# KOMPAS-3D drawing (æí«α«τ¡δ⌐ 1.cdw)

Referenced files in /: k6, h9, s6
Referenced files in E:\Борис\Школа\Детали машин\РГР№2\: 2.cdw
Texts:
  Трехступенчатый коническо- цилиндрический редуктор
  125 1 126 1 127 1 128 0 50 1|SPDS|125 1 126 1 127 1 128 0 50 1
  129 1 130 1 131 1 132 0 50 1|SPDS|129 1 130 1 131 1 132 0 50 1
  min
  max
  Уровень
  масла
  Технические характеристики:
  1. Частота вращения ведущего вала n   = 1455,0 об/мин.
  2. Мощность на ведущем валу N  = 5,78 КВт.
  3. Крутящий момент на тихоходном валу Т  = 3220 Нм.
  4. Общее передаточное число Uобщ = 91.
  5. Коеффициент полезного действия   = 0,845
  Symbol type A
  Технические требования:
  1. Коническая закрутая пара должна иметь боковой зазор в зацеплении 0,2 мм.
  2. Пятно касания конических зубьев:
  Регулировку осуществляют путем перемещения ведущего вала через добавление регулировочных
  прокладок.
  3. Роликоподшипники регулируют при помощи установочной гайки и прокладок.
  4. Редуктор залить машинным маслом марки И-70А ГОСТ 20799-75.
  5. Цилиндрическая зубчатая пара должна иметь боковой зазор в зацеплении 0,15 мм.
  6. Пятно контакта цилиндрических зубьев:
  7. Плоскость разьема редуктора покрыть щелочным лаком или жидким стеклом.
  8. Редуктор подвергнуть холодной обкатке в течении двух часов, при этом зубчатые пары
  должны работать с равномерным шумом.
  Трехступенчатый коническо-
  цилиндрический редуктор
  ДГТУ
  Кафедра ОКМ
Dimensions and other numbers on the sheet: 2; 29; 30; 31; 32; 40; 41; 42; 44; 45; 46; 50; 51; 160; 378,46; 0,06; 218,46; 249,67; 628,13; 1027; 35; 38; 72; 84; 60; 56; 90; 85; 100; 485; 230; 6 отв.; 24; 405; 465; 490; 1; 3; 4; 5; 6; 7; 8; 9; 10; 11; 12; 13; 14; 15; 16; 17; 18; 19; 20; 21; 22; 23; 25; 26; 27; 28; 33; 34; 36; 37; 39; 43; 47; 48; 49; 52; 53; 54; 215; 220; 870; 1:2,5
